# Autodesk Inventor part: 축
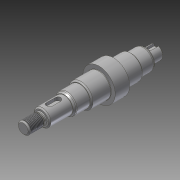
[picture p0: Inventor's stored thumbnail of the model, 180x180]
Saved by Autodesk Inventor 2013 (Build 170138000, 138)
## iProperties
Created: 2019-09
Part Number: 축
Material: 강철, 연강
Document SubType Name: Modeling
Designer: mduedu
Density: 7.86 g/cm^3
Mass: 210.278 g
Surface Area: 69.4769 cm^2
Volume: 26.7529 cm^3
Author: mduedu
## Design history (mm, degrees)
sketch "스케치1"
  geometry: L1 (0, 0)-(15, 0); L2 (15, 0)-(15, 5); L3 (15, 5)-(0, 5); L4 (0, 5)-(0, 0); L5 (15, 0)-(34, 0); L6 (34, 0)-(34, 7); L7 (34, 7)-(15, 7); L8 (15, 7)-(15, 0); L9 (34, 0)-(47, 0); L10 (47, 0)-(47, 8.5); L11 (47, 8.5)-(34, 8.5); L12 (34, 8.5)-(34, 0); L13 (47, 0)-(63, 0); L14 (63, 0)-(63, 10); L15 (63, 10)-(47, 10); L16 (47, 10)-(47, 0); L17 (63, 0)-(75, 0); L18 (75, 0)-(75, 13.5); L19 (75, 13.5)-(63, 13.5); L20 (63, 13.5)-(63, 0); L21 (75, 0)-(90, 0); L22 (90, 0)-(90, 10); L23 (90, 10)-(75, 10); L24 (75, 10)-(75, 0); L25 (90, 0)-(102, 0); L26 (102, 0)-(102, 8.5); L27 (102, 8.5)-(90, 8.5); L28 (90, 8.5)-(90, 0); L29 (102, 0)-(111, 0); L30 (111, 0)-(111, 5.5); L31 (111, 5.5)-(102, 5.5); L32 (102, 5.5)-(102, 0)
  constraints: 64 end point, 16 parallel, 8 horizontal, 8 perpendicular
  dimensions: "d0" = 111 distance between parallel lines of L30 L4; "d2" = 15 distance of L2.end L3.end; "d3" = 19 distance of L6.end L7.end; "d4" = 12 distance of L18.end L19.end; "d5" = 15 distance of L22.end L23.end; "d6" = 12 distance of L26.end L27.end; "d7" = 9 distance of L30.end L31.end; "d8" = 16 distance of L14.end L15.end; "d9" = 10 diameter of L3 L1; "d10" = 14 diameter of L7 L5; "d11" = 17 diameter of L11 L9; "d12" = 20 diameter of L15 L13; "d13" = 27 diameter of L19 L17; "d14" = 20 diameter of L23 L21; "d15" = 17 diameter of L27 L25; "d16" = 11 diameter of L31 L29
revolve "회전1" sketch "스케치1" stored, may be unused: angle "d17" = 90 deg
sketch "스케치2"
  geometry: L1 (0, -5)-(0, 5) reference; L2 (0, 5)-(15, 5) reference; L3 (15, 5)-(15, 7) reference; L4 (15, 7)-(34, 7) reference; L5 (34, 7)-(34, 8.5) reference; L6 (34, 8.5)-(47, 8.5) reference; L7 (47, 8.5)-(47, 10) reference; L8 (47, 10)-(63, 10) reference; L9 (63, 10)-(63, 13.5) reference; L10 (63, 13.5)-(75, 13.5) reference; L11 (75, 13.5)-(75, 10) reference; L12 (75, 10)-(90, 10) reference; L13 (90, 10)-(90, 8.5) reference; L14 (90, 8.5)-(102, 8.5) reference; L15 (102, 8.5)-(102, 5.5) reference; L16 (102, 5.5)-(111, 5.5) reference; L17 (111, 5.5)-(111, -5.5) reference; L18 (111, -5.5)-(102, -5.5) reference; L19 (102, -5.5)-(102, -8.5) reference; L20 (102, -8.5)-(90, -8.5) reference; L21 (90, -8.5)-(90, -10) reference; L22 (90, -10)-(75, -10) reference; L23 (75, -10)-(75, -13.5) reference; L24 (75, -13.5)-(63, -13.5) reference; L25 (63, -13.5)-(63, -10) reference; L26 (63, -10)-(47, -10) reference; L27 (47, -10)-(47, -8.5) reference; L28 (47, -8.5)-(34, -8.5) reference; L29 (34, -8.5)-(34, -7) reference; L30 (34, -7)-(15, -7) reference; L31 (15, -7)-(15, -5) reference; L32 (15, -5)-(0, -5) reference; L33 (0, 0)-(111, 0); L34 (15, 5)-(12.014, 5); L35 (13.4, 4.2)-(15, 4.2); L36 (15, 4.2)-(15, 5); L37 (12.014, 5)-(13.4, 4.2)
  constraints: 10 end point, 1 horizontal, 1 midpoint, 1 parallel, 1 vertical
  dimensions: "d18" = 30 deg angle of L2 L37; "d19" = 8.4 diameter of L35 L33; "d21" = 2.986 distance from line of L34.end L36
revolve "회전2" sketch "스케치2" stored, may be unused: angle "d22" = 90 deg
fillet "모깎기1" dims "d23" = 0.6
feature "스레드1" dims "d24" = 10, "d25" = 0
chamfer "모따기1" distance "d26" = 1; stored, may be unused: second distance "d27" = 2, angle "d28" = 45 deg
chamfer "모따기2" distance "d29" = 1; stored, may be unused: second distance "d30" = 2, angle "d31" = 45 deg
chamfer "모따기3" distance "d32" = 1.819; stored, may be unused: second distance "d33" = 2, angle "d34" = 30 deg
fillet "모깎기2" dims "d35" = 2
chamfer "모따기4" distance "d36" = 1; stored, may be unused: second distance "d37" = 2, angle "d38" = 30 deg
fillet "모깎기3" dims "d39" = 0.3
chamfer "모따기5" distance "d40" = 1; stored, may be unused: second distance "d41" = 2, angle "d42" = 30 deg
chamfer "모따기6" distance "d43" = 1.819; stored, may be unused: second distance "d44" = 2, angle "d45" = 30 deg
chamfer "모따기7" distance "d46" = 0.5; stored, may be unused: second distance "d47" = 2, angle "d48" = 30 deg
fillet "모깎기4" dims "d49" = 2
node "작업 평면1"
sketch "스케치3" dims "d51" = 12
  geometry: L1 (3, -2.5)-(-4, -2.5); L2 (-4, -2.5)-(-4, 2.5); L3 (-4, 2.5)-(3, 2.5); L4 (3, 2.5)-(3, -2.5); L5 (-9.5, 7.45)-(-9.5, -7.45) reference; 3 further points
  constraints: 8 end point, 2 midpoint, 2 parallel, 2 vertical alignment, 1 horizontal, 1 horizontal alignment, 1 perpendicular, 4 other
  dimensions: "d50" = 3 dimension on L5; "d52" = 5 distance between parallel lines of L3 L1
extrude "돌출1" cut sketch "스케치3" distance "d53" = 3; taper "d54" = 0 deg
node "작업 평면3"
sketch "스케치4"
  geometry: L1 (-4.5, -5)-(-4.5, 5) reference; L2 (-4.5, -2)-(1.5, -2); L3 (1.5, -2)-(1.5, 2); L4 (1.5, 2)-(-4.5, 2); L5 (-4.5, 2)-(-4.5, -2); 3 further points
  constraints: 8 end point, 2 horizontal alignment, 2 midpoint, 2 parallel, 1 horizontal, 1 perpendicular, 1 point on line, 1 vertical alignment, 2 other
  dimensions: "d55" = 4 distance between parallel lines of L4 L2; "d57" = 8 dimension on L1
extrude "돌출2" cut sketch "스케치4" distance "d58" = 2.5; taper "d59" = 0 deg
sketch "스케치5"
  geometry: A1 r 5.5 centre (2, -3) between (0, 2.123) and (4, 2.123) reference; 2 further points
  constraints: 1 point on circle
hole "구멍1" sketch "스케치5" at (2, -8.5) diameter "d60" = 2.459; stored, may be unused: countersink angle "d64" = 90 deg, drill point angle "d66" = 118 deg; dims "d61" = 6, "d62" = 4, "d63" = 2, "d65" = 5
fillet "모깎기5" dims "d67" = 1
node "솔리드1"
node "절단 모서리 투영1"
